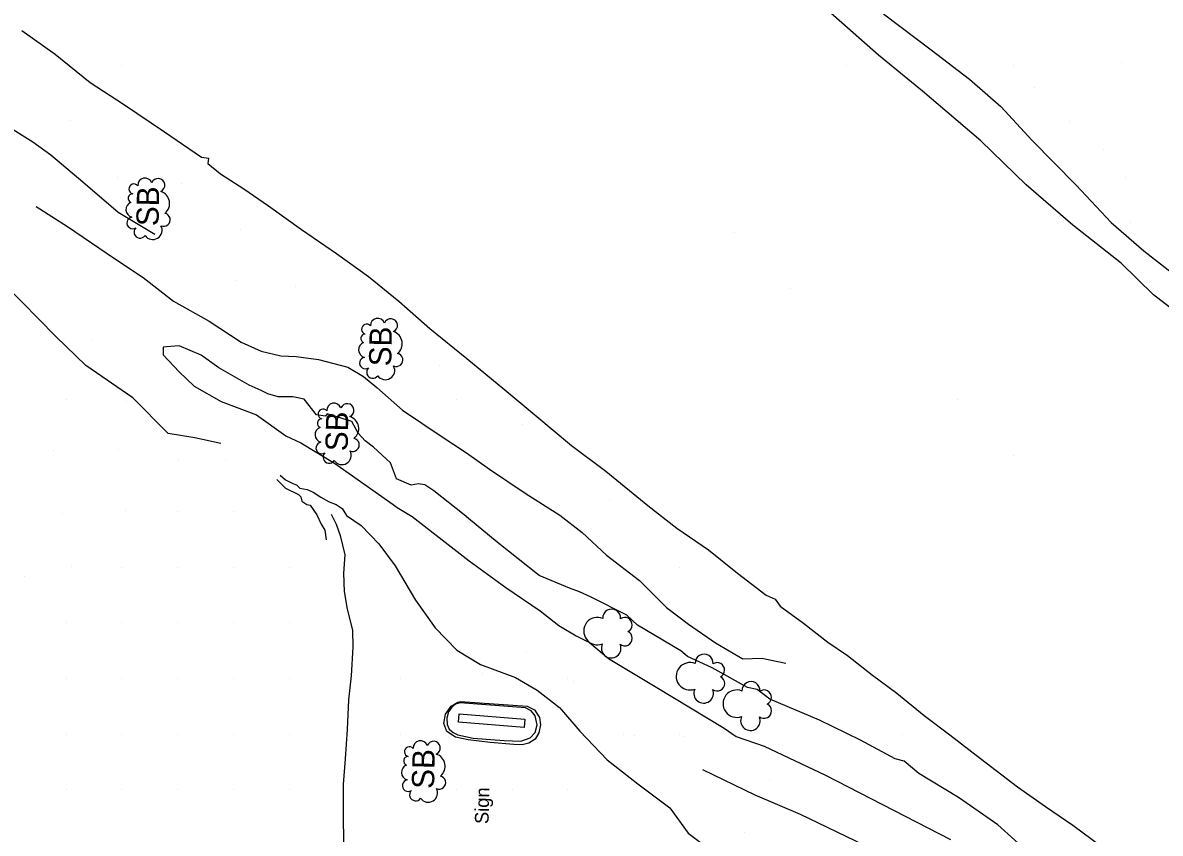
# Model space of a CAD drawing. Extents: x 19528164 to 19545171, y 7585743 to 7602745.
# Drawn here: x 19530964.4 to 19531372.6, y 7590624.5 to 7590915.4 of the extents above; entities that cross this region are included whole.
import ezdxf

# ---------------------------------------------------------------- set-up
doc = ezdxf.new("R2010")
doc.units = 0
for name, color, linetype in [('Default', 7, 'Continuous'), ('PhoBreakLine', 7, 'Continuous'), ('PhoISAEPoints', 7, 'Continuous'), ('PhoNotesDesign', 7, 'Continuous'), ('PhoRetainingWall', 7, 'Continuous'), ('PhoRipRap', 7, 'Continuous'), ('PhoVegetation', 7, 'Continuous'), ('SurAlignment', 7, 'Continuous')]:
    doc.layers.add(name, color=color, linetype=linetype)

# ---------------------------------------------------------------- blocks, each defined once
blk = doc.blocks.new('SHRUB')
at = {"layer": 'Default'}
for centre, radius, start, end in [((-8.82, 2.41), 2.18, 45.3455, 236.8073), ((-5.57, 5.14), 2.08, 10.5948, 214.3611), ((-0.81, 4.83), 2.81, 22.6036, 165.7836), ((3.27, 5.33), 1.59, 0.4605, 158.7839), ((6.61, 4.92), 1.8, 311.3936, 166.4114), ((-8.06, -2.12), 3.34, 125.8289, 299.2848), ((8, 0.98), 2.6, 290.9039, 94.3687), ((8.09, -3.71), 2.42, 204.8294, 69.8871), ((-4.25, -5.95), 2.36, 157.0258, 349.7602), ((1.54, -3.45), 4.54, 220.0183, 343.6977)]:
    blk.add_arc(centre, radius, start, end, dxfattribs=at)
blk.add_text('SB', height=7.998, dxfattribs=at).set_placement((-6.62, -4.17))

msp = doc.modelspace()

# ---------------------------------------------------------------- linework, layer by layer
at = {"layer": 'PhoBreakLine'}
for points in [[(19531389.01, 7590803.2), (19531370.23, 7590817.71), (19531358.63, 7590829.09), (19531341.24, 7590842.72), (19531324.47, 7590857.16), (19531308.26, 7590872.98), (19531287.25, 7590890.86), (19531271.52, 7590903.7), (19531253.31, 7590919.77), (19531236.08, 7590936.44), (19531221.81, 7590950.2), (19531203.65, 7590966.12), (19531186.36, 7590980.73), (19531158.52, 7591003.42), (19531136.83, 7591020.26), (19531118.52, 7591034.91)], [(19531273.34, 7590918.6), (19531290.38, 7590905.61), (19531304.19, 7590895.12), (19531315.39, 7590885.35), (19531326.68, 7590873.09), (19531342.41, 7590857.04), (19531354.99, 7590843.63), (19531366.68, 7590833.46), (19531380.39, 7590822.89)], [(19530964.13, 7590912.57), (19530975.99, 7590904.09), (19530988.65, 7590893.91)], [(19530988.65, 7590893.91), (19531000.61, 7590886.16), (19531015.25, 7590876.28), (19531028.59, 7590867.14), (19531031.05, 7590866.81), (19531030.88, 7590864.82), (19531035.37, 7590861.13), (19531043.71, 7590855.74), (19531052.65, 7590849.7), (19531064.39, 7590841.15), (19531077.01, 7590832.54), (19531088.46, 7590824.27), (19531099.33, 7590815.5), (19531110.53, 7590805.69), (19531123.8, 7590794.82), (19531137.45, 7590783.58), (19531148.16, 7590774.59), (19531161.32, 7590763.69), (19531173.65, 7590754.4), (19531188.76, 7590742.06), (19531188.79, 7590742.1), (19531199.08, 7590733.91), (19531210.49, 7590726.22), (19531220.87, 7590717.84), (19531231.24, 7590709.98), (19531234.38, 7590708.53), (19531236.25, 7590705.93), (19531244.62, 7590699.92), (19531253.32, 7590693.02), (19531260.44, 7590688.29), (19531269.32, 7590681.2), (19531278.06, 7590674.72), (19531287.94, 7590666.78), (19531297.14, 7590659.76), (19531308.08, 7590651.3), (19531321.4, 7590641.11), (19531331.42, 7590634.02), (19531341.22, 7590627.34), (19531351.39, 7590619.79)], [(19530959.02, 7590878.21), (19530968.04, 7590872.67), (19530974.46, 7590867.93), (19530986.02, 7590858.32), (19530998.62, 7590847.43), (19531011.87, 7590839.5)], [(19530969.27, 7590849.41), (19530980.48, 7590842.26), (19530997.35, 7590830.73), (19531007.66, 7590823.96), (19531018.51, 7590815.45), (19531031.33, 7590808.29), (19531042.8, 7590800.75), (19531050, 7590797.45), (19531057.09, 7590795.8), (19531062.59, 7590795.59), (19531070.49, 7590794.51), (19531081.1, 7590791.8), (19531086.71, 7590788.38), (19531091.53, 7590784.49), (19531100.65, 7590776.36), (19531114.92, 7590766.81), (19531123.65, 7590760.99), (19531131.91, 7590755.18), (19531144.77, 7590746.53), (19531157.14, 7590738.58), (19531165.14, 7590732.41), (19531173.94, 7590724.29), (19531185.75, 7590715.19), (19531195.42, 7590705.54), (19531203.33, 7590699.48), (19531212.97, 7590692.78), (19531222.82, 7590687.05), (19531229.63, 7590687.34), (19531238.23, 7590685.52)], [(19531035.5, 7590764.34), (19531026.19, 7590766.39), (19531016.54, 7590767.97), (19531003.91, 7590780.8), (19530987.01, 7590792.31), (19530976.29, 7590802.81), (19530958.03, 7590821.4), (19530940.9, 7590830.2)], [(19531056.83, 7590752.97), (19531058.74, 7590751.26), (19531061.35, 7590749.96), (19531062.7, 7590749.53), (19531063.81, 7590748.36), (19531066.49, 7590747.83), (19531068.68, 7590746.87), (19531071.33, 7590745.04), (19531074.35, 7590743.44), (19531076.92, 7590742.46), (19531079.03, 7590741.04), (19531080.58, 7590738.47)], [(19531055.57, 7590751.47), (19531058.65, 7590748.38), (19531063.35, 7590746.08), (19531064.24, 7590745.2), (19531064.54, 7590743.72), (19531066.31, 7590742.42), (19531067.54, 7590742.25), (19531069.9, 7590738.8), (19531071.47, 7590735.41), (19531072.8, 7590733.31), (19531073.31, 7590729.82)], [(19531075.06, 7590738.97), (19531076.92, 7590735.39), (19531078.28, 7590731.33), (19531079.94, 7590724.4), (19531079.57, 7590717.79), (19531079.72, 7590711.26), (19531080.85, 7590704.85), (19531082.78, 7590697.38), (19531082.88, 7590691.28), (19531082.23, 7590680.95), (19531081.34, 7590672.39), (19531080.82, 7590661.65), (19531080.08, 7590651.13), (19531079.36, 7590642.01), (19531079.38, 7590632.2), (19531079.51, 7590619.85), (19531080.52, 7590609.43), (19531080.41, 7590603.64)], [(19531080.58, 7590738.47), (19531085.85, 7590734.95), (19531092.23, 7590728.4), (19531098.1, 7590720.49), (19531105.3, 7590708.18), (19531112.45, 7590698.15), (19531120.19, 7590690.13), (19531128.74, 7590685), (19531141.19, 7590680.34), (19531149.05, 7590675.78), (19531157.04, 7590669.63), (19531164.3, 7590661.14), (19531174.08, 7590650.77), (19531185.14, 7590642.26), (19531196.66, 7590633.58), (19531203.19, 7590624.48), (19531210.49, 7590618.95)], [(19531208.38, 7590647.38), (19531227.13, 7590638.21), (19531243.35, 7590631.28), (19531266.25, 7590620.36), (19531286.98, 7590607.47), (19531312.44, 7590593), (19531327.75, 7590582.63), (19531347.3, 7590567.18), (19531362.63, 7590553.26), (19531381.47, 7590538.77), (19531408.24, 7590519.71), (19531431.34, 7590501.52), (19531458.35, 7590481.63), (19531481.37, 7590464.32), (19531504.89, 7590443.59), (19531526.3, 7590427.1), (19531553.87, 7590405.06), (19531578.25, 7590388.02), (19531606.01, 7590366.14), (19531626.88, 7590347.86), (19531658.55, 7590322.46), (19531685.28, 7590301.54), (19531706.02, 7590284.67), (19531738.41, 7590257.78)]]:
    msp.add_lwpolyline(points, dxfattribs=at)
msp.add_lwpolyline([(19531140.64, 7590656.31), (19531132.15, 7590657.08), (19531124.3, 7590657.97), (19531119.73, 7590658.95), (19531116.63, 7590660.96), (19531115.5, 7590663.85), (19531116.17, 7590667.26), (19531118.12, 7590670.1), (19531120.49, 7590671.53), (19531121.56, 7590671.74), (19531145.39, 7590670.11), (19531148.05, 7590668.71), (19531149.82, 7590666.04), (19531150.17, 7590663.35), (19531149.63, 7590660.5), (19531148.28, 7590658.29), (19531146.03, 7590656.8), (19531143.67, 7590656.25), (19531143.67, 7590656.23)], close=True, dxfattribs=at)
at = {"layer": 'PhoISAEPoints'}
for p, q in [((19531000, 7590900), (19531000, 7590900)), ((19531260, 7590900), (19531260, 7590900)), ((19531320, 7590900), (19531320, 7590900)), ((19531358.56, 7590901.04), (19531358.56, 7590901.04)), ((19531327.37, 7590892.29), (19531327.37, 7590892.29)), ((19530981.66, 7590880.34), (19530981.66, 7590880.34)), ((19531340, 7590880), (19531340, 7590880)), ((19531352.13, 7590869.73), (19531352.13, 7590869.73)), ((19530998.28, 7590859.7), (19530998.28, 7590859.7)), ((19531021.43, 7590857.77), (19531021.43, 7590857.77)), ((19531360, 7590860), (19531360, 7590860)), ((19531361.92, 7590843.82), (19531361.92, 7590843.82)), ((19531042.58, 7590841.24), (19531042.58, 7590841.24)), ((19531220, 7590840), (19531220, 7590840)), ((19531040.79, 7590822.71), (19531040.79, 7590822.71)), ((19531062.17, 7590820.84), (19531062.17, 7590820.84)), ((19531240, 7590820), (19531240, 7590820)), ((19530989.23, 7590801.56), (19530989.23, 7590801.56)), ((19531100, 7590800), (19531100, 7590800)), ((19531114.11, 7590792.33), (19531114.11, 7590792.33)), ((19530980, 7590780), (19530980, 7590780)), ((19531001.82, 7590779.44), (19531001.82, 7590779.44)), ((19531120, 7590780), (19531120, 7590780)), ((19531300, 7590780), (19531300, 7590780)), ((19531143.72, 7590771.14), (19531143.72, 7590771.14)), ((19530975.38, 7590761.92), (19530975.38, 7590761.92)), ((19530998.88, 7590762.3), (19530998.88, 7590762.3)), ((19531320, 7590760), (19531320, 7590760)), ((19531020.43, 7590758.65), (19531020.43, 7590758.65)), ((19531037.18, 7590758.79), (19531037.18, 7590758.79)), ((19531175.02, 7590743.9), (19531175.02, 7590743.9)), ((19531001.38, 7590740.46), (19531001.38, 7590740.46)), ((19531020, 7590740), (19531020, 7590740)), ((19531040, 7590740), (19531040, 7590740)), ((19530978.78, 7590739.15), (19530978.78, 7590739.15)), ((19530981.79, 7590720.04), (19530981.79, 7590720.04)), ((19531000, 7590720), (19531000, 7590720)), ((19531020, 7590720), (19531020, 7590720)), ((19531040, 7590720), (19531040, 7590720)), ((19531060, 7590720), (19531060, 7590720)), ((19531200, 7590720), (19531200, 7590720)), ((19530965.2, 7590716.64), (19530965.2, 7590716.64)), ((19530980, 7590700), (19530980, 7590700)), ((19531000, 7590700), (19531000, 7590700)), ((19531020, 7590700), (19531020, 7590700)), ((19531040, 7590700), (19531040, 7590700)), ((19531060, 7590700), (19531060, 7590700)), ((19531145.15, 7590689.31), (19531145.15, 7590689.31)), ((19530980, 7590680), (19530980, 7590680)), ((19531000, 7590680), (19531000, 7590680)), ((19531020, 7590680), (19531020, 7590680)), ((19531040, 7590680), (19531040, 7590680)), ((19531060, 7590680), (19531060, 7590680)), ((19531100, 7590680), (19531100, 7590680)), ((19531129.36, 7590681.93), (19531129.36, 7590681.93)), ((19531160, 7590680), (19531160, 7590680)), ((19531162.12, 7590679.11), (19531162.12, 7590679.11)), ((19530980, 7590660), (19530980, 7590660)), ((19531000, 7590660), (19531000, 7590660)), ((19531020, 7590660), (19531020, 7590660)), ((19531040, 7590660), (19531040, 7590660)), ((19531060, 7590660), (19531060, 7590660)), ((19531100, 7590660), (19531100, 7590660)), ((19531180, 7590660), (19531180, 7590660)), ((19531180, 7590660), (19531180, 7590660)), ((19531183.95, 7590659.7), (19531183.95, 7590659.7)), ((19531200, 7590660), (19531200, 7590660)), ((19531200, 7590660), (19531200, 7590660)), ((19531201.91, 7590659.22), (19531201.91, 7590659.22)), ((19531280, 7590660), (19531280, 7590660)), ((19531232.3, 7590643.45), (19531232.3, 7590643.45)), ((19530980, 7590640), (19530980, 7590640)), ((19531000, 7590640), (19531000, 7590640)), ((19531020, 7590640), (19531020, 7590640)), ((19531040, 7590640), (19531040, 7590640)), ((19531060, 7590640), (19531060, 7590640)), ((19531100, 7590640), (19531100, 7590640)), ((19531120, 7590640), (19531120, 7590640)), ((19531140, 7590640), (19531140, 7590640)), ((19531160, 7590640), (19531160, 7590640)), ((19531223.56, 7590624.61), (19531223.56, 7590624.61))]:
    msp.add_line(p, q, dxfattribs=at)
at = {"layer": 'PhoRetainingWall'}
msp.add_lwpolyline([(19531126.08, 7590658.63), (19531137.14, 7590657.71), (19531143.19, 7590657.48), (19531146.52, 7590658.71), (19531148.35, 7590660.59), (19531149.06, 7590663.32), (19531148.35, 7590666.65), (19531146.82, 7590668.35), (19531144.88, 7590669.51), (19531121.33, 7590671.32), (19531119.66, 7590670.78), (19531118.38, 7590669.74), (19531117.15, 7590668.03), (19531116.56, 7590665.79), (19531116.73, 7590663.52), (19531117.48, 7590661.81), (19531118.83, 7590660.68), (19531120.51, 7590659.8)], close=True, dxfattribs=at)
at = {"layer": 'PhoRipRap'}
msp.add_lwpolyline([(19531326.5, 7590616.42), (19531314.39, 7590627.46), (19531300.19, 7590637.26), (19531286.02, 7590645.88), (19531280.67, 7590650.34), (19531277.52, 7590651.15), (19531265.04, 7590657.9), (19531250.32, 7590665.01), (19531232.55, 7590672.54), (19531227.91, 7590676.12), (19531224.54, 7590676.79), (19531211.87, 7590683.79), (19531203.01, 7590687.89), (19531200.54, 7590689.94), (19531184.99, 7590699.15), (19531181.25, 7590702.79), (19531168.35, 7590709.22), (19531164.17, 7590711.13), (19531160.68, 7590712.47), (19531149.68, 7590717.03), (19531134.63, 7590728.98), (19531124.32, 7590737.44), (19531122.82, 7590738.7), (19531111.89, 7590747.34), (19531108.73, 7590749.48), (19531106.42, 7590749.85), (19531103.82, 7590749.45), (19531098.56, 7590751.62), (19531096.36, 7590757.4), (19531090.33, 7590762.99), (19531087.29, 7590765.26), (19531084.75, 7590768.11), (19531082.52, 7590772.29), (19531073.71, 7590775.05), (19531073.06, 7590774.14), (19531069.87, 7590774.7), (19531065.42, 7590780.22), (19531061.31, 7590781.11), (19531056.12, 7590781.07), (19531052.42, 7590782.24), (19531049.97, 7590783.39), (19531045.71, 7590785.3), (19531034.79, 7590791.48), (19531028.41, 7590796.02), (19531020.54, 7590799.37), (19531016.05, 7590799.09), (19531014.76, 7590798.92), (19531014.81, 7590796.13), (19531020.53, 7590790.07), (19531025.89, 7590784.95), (19531035.56, 7590779.42), (19531048.26, 7590774.62), (19531058.84, 7590767.14), (19531058.84, 7590767.14), (19531064.25, 7590764.65), (19531076.24, 7590757.34), (19531097.32, 7590742.42), (19531098.77, 7590741.41), (19531104.2, 7590738.2), (19531124.59, 7590722.3), (19531137.83, 7590712.64), (19531150.13, 7590704.34), (19531156.81, 7590699), (19531163.07, 7590695.34), (19531167.76, 7590692.9), (19531174.61, 7590687.22), (19531191.97, 7590676.72), (19531216.1, 7590662.13), (19531220.45, 7590659.17), (19531230.47, 7590655.68), (19531252.49, 7590645.27), (19531297.33, 7590622.25)], dxfattribs=at)
at = {"layer": 'PhoVegetation'}
for centre, radius, start, end in [((19531175.75, 7590701.73), 3.21, 355.0943, 183.0979), ((19531170.65, 7590697.02), 4.92, 67.3012, 290.8911), ((19531180.46, 7590699.26), 2.67, 295.6203, 124.4995), ((19531180.46, 7590694.43), 2.68, 231.8463, 64.4185), ((19531175.58, 7590690.91), 3.52, 154.5785, 23.6137), ((19531208.92, 7590685.51), 3.21, 355.0943, 183.0979), ((19531203.82, 7590680.8), 4.92, 67.3012, 290.8911), ((19531213.63, 7590683.03), 2.67, 295.6203, 124.4995), ((19531213.63, 7590678.21), 2.68, 231.8463, 64.4185), ((19531225.73, 7590675.69), 3.21, 355.0943, 183.0979), ((19531208.75, 7590674.69), 3.52, 154.5785, 23.6137), ((19531220.63, 7590670.98), 4.92, 67.3012, 290.8911), ((19531230.44, 7590673.22), 2.67, 295.6203, 124.4995), ((19531230.44, 7590668.39), 2.68, 231.8463, 64.4185), ((19531225.56, 7590664.87), 3.52, 154.5785, 23.6137)]:
    msp.add_arc(centre, radius, start, end, dxfattribs=at)
at = {"layer": 'SurAlignment'}
msp.add_lwpolyline([(19531120.98, 7590667.31), (19531144.62, 7590665.36), (19531144.38, 7590662.4), (19531120.73, 7590664.35)], close=True, dxfattribs=at)
msp.add_lwpolyline([(19531132.89, 7590663.86), (19531132.89, 7590663.86), (19531132.89, 7590663.87), (19531132.89, 7590663.87), (19531132.89, 7590663.86), (19531132.89, 7590663.86), (19531132.89, 7590663.86)], dxfattribs=at)

# ---------------------------------------------------------------- block references
at = {"layer": 'PhoVegetation', "xscale": 0.9999999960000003, "yscale": 0.9999999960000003, "rotation": 88.89301078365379}
for p in [(19531009.11, 7590849.01), (19531092.6, 7590798.7), (19531076.97, 7590768.22), (19531107.97, 7590647.04)]:
    msp.add_blockref('SHRUB', p, dxfattribs=at)

# ---------------------------------------------------------------- texts
at = {"layer": 'PhoNotesDesign'}
msp.add_text('Sign', height=4.92, rotation=88.6813, dxfattribs=at).set_placement((19531131.56, 7590627.73))
at = {"layer": 'SurAlignment'}
msp.add_text('X', height=0.00583, rotation=88.6813, dxfattribs=at).set_placement((19531132.89, 7590663.87))

doc.saveas('drawing.dxf')
